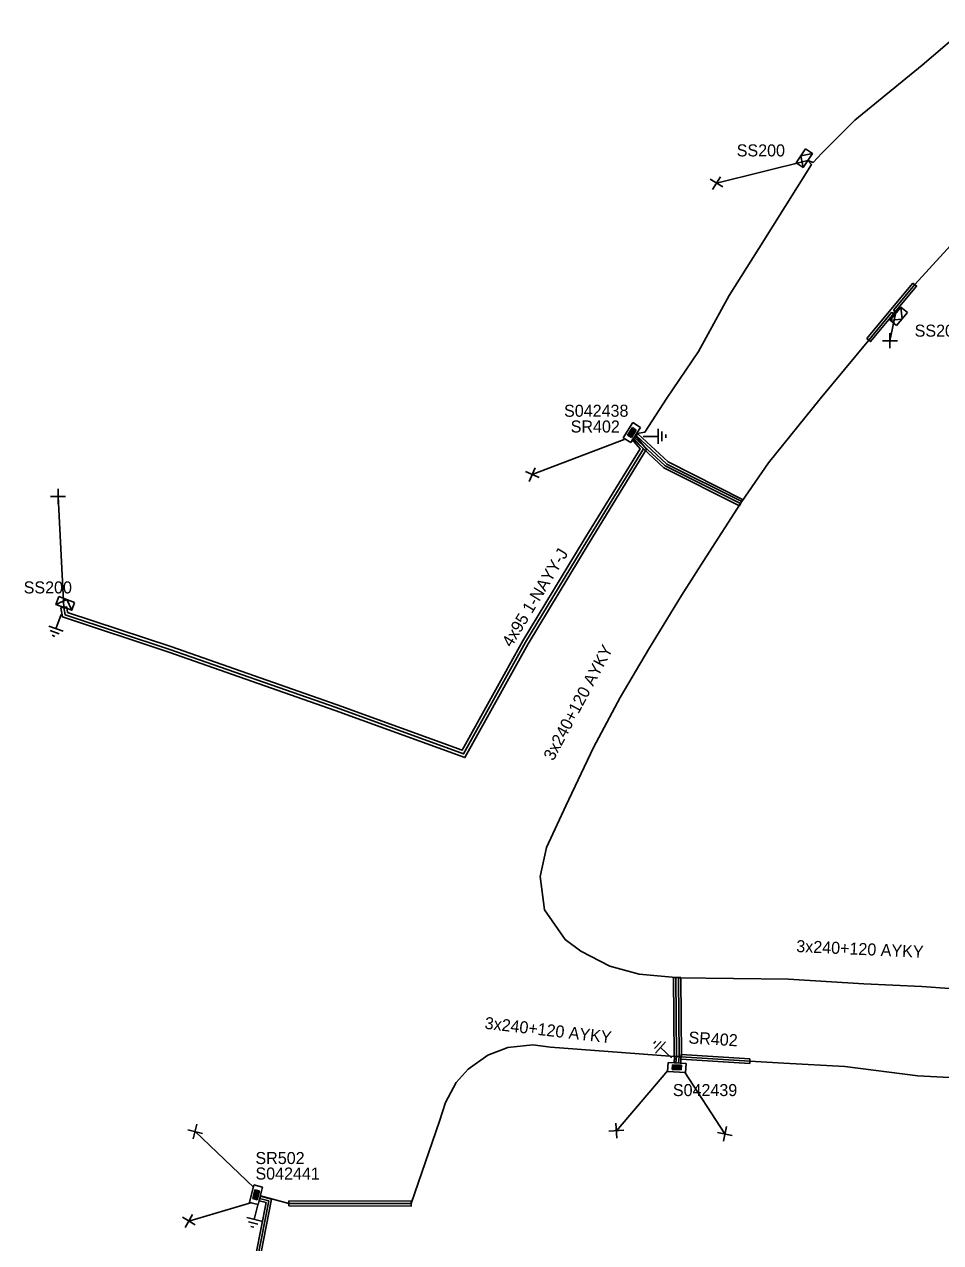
# Model space of a CAD drawing. Extents: x -748492 to -735633, y -1146251 to -1139940.
# Drawn here: x -736997.8 to -736921.6, y -1145084.8 to -1144983.5 of the extents above; entities that cross this region are included whole.
import ezdxf

# ---------------------------------------------------------------- set-up
doc = ezdxf.new("R2010")
doc.units = 0
for name, color, linetype in [('Vrstva 1', 7, 'Continuous'), ('Vrstva 14', 7, 'Continuous'), ('Vrstva 15', 7, 'Continuous'), ('Vrstva 20', 7, 'Continuous'), ('Vrstva 28', 7, 'Continuous'), ('Vrstva 29', 7, 'Continuous'), ('Vrstva 30', 7, 'Continuous'), ('Vrstva 31', 7, 'Continuous'), ('Vrstva 33', 7, 'Continuous'), ('Vrstva 34', 7, 'Continuous'), ('Vrstva 5', 7, 'Continuous'), ('Vrstva 59', 7, 'Continuous'), ('Vrstva 6', 7, 'Continuous'), ('Vrstva 8', 7, 'Continuous'), ('Vrstva 9', 7, 'Continuous')]:
    doc.layers.add(name, color=color, linetype=linetype)

# ---------------------------------------------------------------- blocks, each defined once
blk = doc.blocks.new('NN800')
at = {"layer": 'Vrstva 1'}
for points in [[(-0.44, 0.44), (0.44, -0.44)], [(-0.44, -0.44), (0.44, 0.44)]]:
    blk.add_lwpolyline(points, dxfattribs=at)
blk = doc.blocks.new('NN620')
at = {"layer": 'Vrstva 8'}
for points in [[(0.75, 0), (-0.75, 0)], [(-0.75, 0), (-0.75, -0.75)], [(0.75, -0.75), (0.75, 0)], [(-0.75, -0.75), (0.75, -0.75)], [(0.37, -0.18), (-0.38, -0.18)], [(-0.38, -0.18), (-0.38, -0.56)], [(-0.38, -0.56), (0.37, -0.56)], [(0.32, -0.23), (-0.33, -0.23)], [(-0.33, -0.23), (-0.33, -0.51)], [(-0.33, -0.51), (0.32, -0.51)], [(0.27, -0.27), (-0.28, -0.27)], [(-0.28, -0.27), (-0.28, -0.46)], [(-0.28, -0.46), (0.27, -0.46)], [(0.23, -0.32), (-0.23, -0.32)], [(-0.23, -0.32), (-0.23, -0.42)], [(-0.23, -0.42), (0.23, -0.42)], [(-0.19, -0.37), (0.19, -0.37)], [(0.23, -0.42), (0.23, -0.32)], [(0.27, -0.46), (0.27, -0.27)], [(0.32, -0.51), (0.32, -0.23)], [(0.37, -0.56), (0.37, -0.18)]]:
    blk.add_lwpolyline(points, dxfattribs=at)
blk = doc.blocks.new('NN630')
at = {"layer": 'Vrstva 9'}
for points in [[(0, -0.7), (-0.7, 0)], [(-0.7, -0.7), (-0.7, 0), (0.7, 0), (0.7, -0.7)], [(-0.7, -0.7), (0.7, -0.7)], [(0, -0.7), (0.7, 0)]]:
    blk.add_lwpolyline(points, dxfattribs=at)
blk = doc.blocks.new('NN810')
at = {"layer": 'Vrstva 14'}
for points in [[(0, -0.64), (0, -1.89)], [(0.63, -1.89), (-0.62, -1.89)], [(0.39, -2.2), (-0.4, -2.2)], [(0, -2.52), (-0.12, -2.52)], [(0.14, -2.52), (0, -2.52)]]:
    blk.add_lwpolyline(points, dxfattribs=at)

msp = doc.modelspace()

# ---------------------------------------------------------------- linework, layer by layer
at = {"layer": 'Vrstva 20'}
for points in [[(-736923.87, -1145004.99), (-736923.57, -1145005.25), (-736925.23, -1145007.25), (-736925.59, -1145007.68), (-736927.4, -1145009.86), (-736927.7, -1145009.6), (-736925.7, -1145007.19)], [(-736994.25, -1145031.92), (-736994.18, -1145032.38), (-736985.61, -1145035.21), (-736971.76, -1145040.06), (-736961.36, -1145043.83), (-736956.31, -1145034.73), (-736951.22, -1145026.33), (-736946.57, -1145018.78), (-736947.22, -1145017.99), (-736946.89, -1145017.74), (-736946.03, -1145018.81), (-736950.8, -1145026.59), (-736955.87, -1145034.98), (-736961.14, -1145044.45), (-736971.92, -1145040.53), (-736985.77, -1145035.69), (-736994.62, -1145032.76), (-736994.75, -1145032)], [(-736938.04, -1145022.98), (-736938.3, -1145023.51), (-736944.58, -1145020.37), (-736947.15, -1145017.98), (-736946.75, -1145017.54), (-736944.24, -1145019.87)], [(-736943.13, -1145069.31), (-736943.73, -1145069.32), (-736943.76, -1145066.04), (-736943.78, -1145062.75), (-736943.18, -1145062.75), (-736943.16, -1145066.04)], [(-736937.43, -1145069.49), (-736937.45, -1145069.89), (-736943.18, -1145069.53), (-736943.16, -1145069.13)], [(-736978.15, -1145080.92), (-736977.22, -1145081.18), (-736978.52, -1145087.85), (-736979.83, -1145094.58), (-736981.35, -1145100.88), (-736981.73, -1145100.78), (-736980.23, -1145094.5), (-736978.92, -1145087.77), (-736977.68, -1145081.46), (-736978.26, -1145081.31)], [(-736965.6, -1145081.34), (-736965.6, -1145081.74), (-736975.78, -1145081.72), (-736975.78, -1145081.32)]]:
    msp.add_lwpolyline(points, close=True, dxfattribs=at)
at = {"layer": 'Vrstva 5'}
for points in [[(-736946.8, -1145017.5), (-736946.17, -1145017.39), (-736944.35, -1145014.55), (-736941.71, -1145010.69), (-736939.16, -1145006.04), (-736936.68, -1145002.12), (-736932.31, -1144995.13), (-736932.62, -1144994.8), (-736932.17, -1144994.96), (-736931.45, -1144994.19), (-736928.7, -1144991.45), (-736923.11, -1144986.86), (-736919.13, -1144983.48)], [(-736946.9, -1145017.67), (-736944.35, -1145020.04), (-736938.1, -1145023.17), (-736935.89, -1145019.94), (-736931.59, -1145014.61), (-736927.55, -1145009.73), (-736925.66, -1145007.45), (-736925.32, -1145007.54), (-736925.47, -1145007.22), (-736923.72, -1145005.12), (-736919.82, -1145000.88), (-736914.39, -1144995.56), (-736911.59, -1144992.86), (-736911.14, -1144992.82)], [(-736994.5, -1145031.96), (-736994.4, -1145032.57), (-736985.69, -1145035.45), (-736971.84, -1145040.3), (-736961.25, -1145044.14), (-736956.09, -1145034.85), (-736951.01, -1145026.46), (-736946.27, -1145018.78), (-736947.1, -1145017.94)], [(-736947.02, -1145017.83), (-736944.47, -1145020.2), (-736938.21, -1145023.33), (-736941.06, -1145027.77), (-736943.11, -1145030.97), (-736945.86, -1145035.46), (-736948.22, -1145039.46), (-736950.43, -1145043.61), (-736952.74, -1145048.45), (-736954.34, -1145051.93), (-736954.88, -1145054.33), (-736954.53, -1145057.12), (-736952.8, -1145059.59), (-736951.49, -1145060.56), (-736949.08, -1145061.79), (-736946.65, -1145062.45), (-736943.58, -1145062.75), (-736943.56, -1145066.04), (-736943.53, -1145069.32), (-736943.58, -1145069.83)], [(-736943.38, -1145069.85), (-736943.33, -1145069.32), (-736943.35, -1145066.04), (-736943.38, -1145062.76), (-736934.21, -1145062.88), (-736927.96, -1145063.27), (-736923.12, -1145063.49), (-736918.54, -1145063.81)], [(-736943.74, -1145069.83), (-736943.7, -1145069.3), (-736949.21, -1145068.88), (-736954.01, -1145068.52), (-736955.48, -1145068.35), (-736957.58, -1145068.56), (-736959.24, -1145069.21), (-736960.86, -1145070.35), (-736961.86, -1145071.48), (-736962.75, -1145073.12), (-736963.25, -1145074.68), (-736965.6, -1145081.54), (-736975.78, -1145081.52), (-736978.15, -1145080.9)], [(-736915.55, -1145071.33), (-736923.47, -1145070.91), (-736929.55, -1145070.13), (-736934.61, -1145069.87), (-736937.44, -1145069.69), (-736943.17, -1145069.33), (-736943.17, -1145069.87)], [(-736978.21, -1145081.11), (-736977.45, -1145081.32), (-736978.72, -1145087.81), (-736980.03, -1145094.54), (-736981.54, -1145100.83), (-736982.28, -1145105.06), (-736982.6, -1145107.47)]]:
    msp.add_lwpolyline(points, dxfattribs=at)
at = {"layer": 'Vrstva 59'}
for points in [[(-736932.62, -1144994.8), (-736940.21, -1144996.68)], [(-736925.32, -1145007.54), (-736925.79, -1145009.79)], [(-736947.88, -1145017.99), (-736955.54, -1145020.92)], [(-736994.5, -1145031.96), (-736994.98, -1145022.73)], [(-736944.26, -1145070.48), (-736948.54, -1145075.48)], [(-736942.87, -1145070.59), (-736939.51, -1145075.75)], [(-736978.69, -1145080.21), (-736983.58, -1145075.55)], [(-736978.87, -1145081.44), (-736984.1, -1145082.99)]]:
    msp.add_lwpolyline(points, dxfattribs=at)

# ---------------------------------------------------------------- block references
at = {"layer": 'Vrstva 15'}
for p, rotation in [((-736946.95, -1145017.76), 90.55362782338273), ((-736994.5, -1145031.96), -20.159191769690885), ((-736943.48, -1145069.84), -132.77401117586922), ((-736978.21, -1145081.02), -14.120947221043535)]:
    msp.add_blockref('NN810', p, dxfattribs=dict(at, rotation=rotation))
at = {"layer": 'Vrstva 28'}
for p, rotation in [((-736946.94, -1145017.63), -123.03445544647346), ((-736943.48, -1145069.84), -3.4612332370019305), ((-736978.15, -1145080.9), -104.12094723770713)]:
    msp.add_blockref('NN620', p, dxfattribs=dict(at, rotation=rotation))
at = {"layer": 'Vrstva 31'}
for p, rotation in [((-736932.62, -1144994.8), -123.99649440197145), ((-736925.32, -1145007.54), 50.37978613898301), ((-736994.5, -1145031.96), 159.84080835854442)]:
    msp.add_blockref('NN630', p, dxfattribs=dict(at, rotation=rotation))
at = {"layer": 'Vrstva 34'}
for p, rotation in [((-736940.21, -1144996.68), 13.91193615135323), ((-736925.79, -1145009.79), 45), ((-736955.54, -1145020.92), 20.93211661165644), ((-736994.98, -1145022.73), -45), ((-736983.58, -1145075.55), 30.96375551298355), ((-736948.54, -1145075.48), 49.43641388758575), ((-736939.51, -1145075.75), 123.07068886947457), ((-736984.1, -1145082.99), 14.553605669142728)]:
    msp.add_blockref('NN800', p, dxfattribs=dict(at, rotation=rotation))

# ---------------------------------------------------------------- texts
at = {"layer": 'Vrstva 29'}
for s, p in [('S042438', (-736952.89, -1145016.11)), ('S042439', (-736943.84, -1145072.6)), ('S042441', (-736978.56, -1145079.54))]:
    msp.add_text(s, height=1, dxfattribs=at).set_placement(p)
at = {"layer": 'Vrstva 30'}
for s, p in [('SR402', (-736952.34, -1145017.42)), ('SR502', (-736978.56, -1145078.25))]:
    msp.add_text(s, height=1, dxfattribs=at).set_placement(p)
msp.add_text('SR402', height=1, rotation=356.539, dxfattribs=at).set_placement((-736942.56, -1145068.22))
at = {"layer": 'Vrstva 33'}
for p in [(-736938.53, -1144994.46), (-736923.73, -1145009.45), (-736997.84, -1145030.8)]:
    msp.add_text('SS200', height=1, dxfattribs=at).set_placement(p)
at = {"layer": 'Vrstva 6'}
for s, rotation, p in [('4x95 1-NAYY-J', 58.806, (-736957.27, -1145035.34)), ('3x240+120 AYKY', 61.963, (-736953.78, -1145044.78)), ('3x240+120 AYKY', 357.397, (-736933.59, -1145060.62)), ('3x240+120 AYKY', 353.403, (-736959.53, -1145067))]:
    msp.add_text(s, height=1, rotation=rotation, dxfattribs=at).set_placement(p)

doc.saveas('drawing.dxf')
